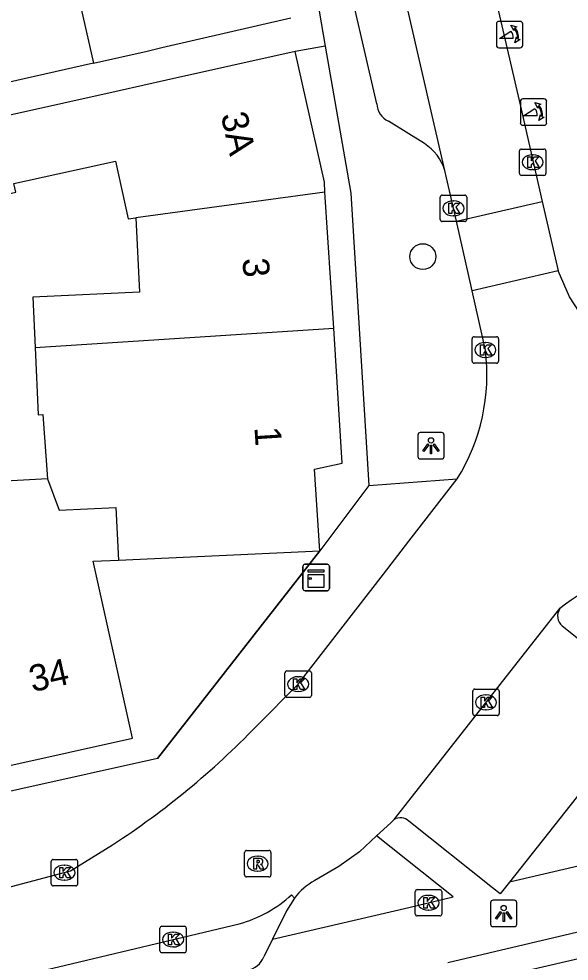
# Model space of a CAD drawing. Extents: x 160861 to 161308, y 384024 to 384878.
# Drawn here: x 160985.24 to 161006.07, y 384696.73 to 384732.38 of the extents above; entities that cross this region are included whole.
import ezdxf

# ---------------------------------------------------------------- set-up
doc = ezdxf.new("R2010")
doc.units = 0
for name, color, linetype in [('IMGEO_Boom', 7, 'Continuous'), ('IMGEO_Kast', 7, 'Continuous'), ('IMGEO_Kolk', 7, 'Continuous'), ('IMGEO_Lichtpunt', 7, 'Continuous'), ('IMGEO_Muur', 7, 'Continuous'), ('IMGEO_Pand', 7, 'Continuous'), ('IMGEO_Pand_nummerreeks', 7, 'Continuous'), ('IMGEO_Parkeervlak_open', 7, 'Continuous'), ('IMGEO_Poller', 7, 'Continuous'), ('IMGEO_Rijbaan_lokaal_open', 7, 'Continuous'), ('IMGEO_Rioolput', 7, 'Continuous'), ('IMGEO_Voetpad_open', 7, 'Continuous')]:
    doc.layers.add(name, color=color, linetype=linetype)

msp = doc.modelspace()

# ---------------------------------------------------------------- linework, layer by layer
at = {"layer": 'IMGEO_Boom'}
msp.add_circle((161000.528, 384723.383), 0.489, dxfattribs=at)
at = {"layer": 'IMGEO_Kast'}
for p, q in [((160995.991, 384710.823), (160995.991, 384711.664)), ((160995.991, 384711.664), (160995.991, 384710.823)), ((160996.066, 384711.748), (160996.907, 384711.748)), ((160996.907, 384711.748), (160996.066, 384711.748)), ((160996.991, 384711.673), (160996.991, 384710.832)), ((160996.991, 384710.832), (160996.991, 384711.673)), ((160996.916, 384710.748), (160996.075, 384710.748)), ((160996.075, 384710.748), (160996.916, 384710.748))]:
    msp.add_line(p, q, dxfattribs=at)
for points in [[(160996.186, 384711.538), (160996.786, 384711.538), (160996.786, 384711.453), (160996.186, 384711.453), (160996.186, 384711.538)], [(160996.186, 384711.363), (160996.786, 384711.363), (160996.786, 384710.874), (160996.186, 384710.874), (160996.186, 384711.363)]]:
    msp.add_lwpolyline(points, dxfattribs=at)
msp.add_circle((160996.27, 384711.212), 0.0377, dxfattribs=at)
for centre, start, end in [((160996.069, 384711.67), 92.4484, 184.2845), ((160996.069, 384711.67), 92.4484, 184.2845), ((160996.913, 384711.67), 2.4484, 94.2845), ((160996.913, 384711.67), 2.4484, 94.2845), ((160996.069, 384710.826), 182.4484, 274.2845), ((160996.069, 384710.826), 182.4484, 274.2845), ((160996.913, 384710.826), 272.4484, 4.2845), ((160996.913, 384710.826), 272.4484, 4.2845)]:
    msp.add_arc(centre, 0.0779, start, end, dxfattribs=at)
at = {"layer": 'IMGEO_Kolk'}
for p, q in [((161004.187, 384726.528), (161004.187, 384727.38)), ((161004.262, 384727.454), (161005.114, 384727.454)), ((161004.675, 384727.234), (161004.7, 384727.234)), ((161005.188, 384727.38), (161005.188, 384726.528)), ((161004.698, 384726.674), (161004.673, 384726.674)), ((161005.114, 384726.454), (161004.262, 384726.454)), ((161001.189, 384724.785), (161001.189, 384725.637)), ((161001.264, 384725.711), (161002.116, 384725.711)), ((161001.677, 384725.491), (161001.702, 384725.491)), ((161002.19, 384725.637), (161002.19, 384724.785)), ((161002.116, 384724.711), (161001.264, 384724.711)), ((161001.7, 384724.931), (161001.675, 384724.931)), ((161002.395, 384719.428), (161002.395, 384720.28)), ((161002.47, 384720.354), (161003.322, 384720.354)), ((161002.883, 384720.134), (161002.908, 384720.134)), ((161003.396, 384720.28), (161003.396, 384719.428)), ((161003.322, 384719.354), (161002.47, 384719.354)), ((161002.906, 384719.574), (161002.881, 384719.574)), ((160995.312, 384706.788), (160995.312, 384707.64)), ((160995.387, 384707.714), (160996.239, 384707.714)), ((160996.313, 384707.64), (160996.313, 384706.788)), ((160995.8, 384707.494), (160995.825, 384707.494)), ((160995.823, 384706.934), (160995.798, 384706.934)), ((161002.419, 384706.098), (161002.419, 384706.95)), ((161002.494, 384707.024), (161003.346, 384707.024)), ((161003.42, 384706.95), (161003.42, 384706.098)), ((160996.239, 384706.714), (160995.387, 384706.714)), ((161002.907, 384706.804), (161002.932, 384706.804)), ((161002.93, 384706.244), (161002.905, 384706.244)), ((161003.346, 384706.024), (161002.494, 384706.024)), ((160986.463, 384699.656), (160986.463, 384700.508)), ((160986.538, 384700.582), (160987.39, 384700.582)), ((160987.464, 384700.508), (160987.464, 384699.656)), ((160986.951, 384700.362), (160986.976, 384700.362)), ((160986.974, 384699.802), (160986.949, 384699.802)), ((160987.39, 384699.582), (160986.538, 384699.582)), ((161000.32, 384699.444), (161001.172, 384699.444)), ((161000.245, 384698.518), (161000.245, 384699.37)), ((161000.733, 384699.224), (161000.758, 384699.224)), ((161001.246, 384699.37), (161001.246, 384698.518)), ((161001.172, 384698.444), (161000.32, 384698.444)), ((161000.756, 384698.664), (161000.731, 384698.664)), ((160990.576, 384697.127), (160990.576, 384697.979)), ((160990.651, 384698.053), (160991.503, 384698.053)), ((160991.577, 384697.979), (160991.577, 384697.127)), ((160991.064, 384697.833), (160991.089, 384697.833)), ((160991.087, 384697.273), (160991.062, 384697.273)), ((160991.503, 384697.053), (160990.651, 384697.053))]:
    msp.add_line(p, q, dxfattribs=at)
for points in [[(161004.187, 384726.528), (161004.187, 384727.38)], [(161004.262, 384727.454), (161005.114, 384727.454)], [(161005.188, 384727.38), (161005.188, 384726.528)], [(161004.508, 384727.154), (161004.631, 384727.154), (161004.631, 384727.003), (161004.761, 384727.154), (161004.925, 384727.154), (161004.779, 384727.003), (161004.932, 384726.754), (161004.78, 384726.754), (161004.695, 384726.918), (161004.631, 384726.851), (161004.631, 384726.754), (161004.508, 384726.754), (161004.508, 384727.154)], [(161005.114, 384726.454), (161004.262, 384726.454)], [(161001.189, 384724.785), (161001.189, 384725.637)], [(161001.264, 384725.711), (161002.116, 384725.711)], [(161001.51, 384725.411), (161001.633, 384725.411), (161001.633, 384725.26), (161001.763, 384725.411), (161001.927, 384725.411), (161001.781, 384725.26), (161001.934, 384725.011), (161001.782, 384725.011), (161001.697, 384725.175), (161001.633, 384725.108), (161001.633, 384725.011), (161001.51, 384725.011), (161001.51, 384725.411)], [(161002.19, 384725.637), (161002.19, 384724.785)], [(161002.116, 384724.711), (161001.264, 384724.711)], [(161002.395, 384719.428), (161002.395, 384720.28)], [(161002.47, 384720.354), (161003.322, 384720.354)], [(161002.716, 384720.054), (161002.839, 384720.054), (161002.839, 384719.903), (161002.969, 384720.054), (161003.133, 384720.054), (161002.987, 384719.903), (161003.14, 384719.654), (161002.988, 384719.654), (161002.903, 384719.818), (161002.839, 384719.751), (161002.839, 384719.654), (161002.716, 384719.654), (161002.716, 384720.054)], [(161003.396, 384720.28), (161003.396, 384719.428)], [(161003.322, 384719.354), (161002.47, 384719.354)], [(160995.312, 384706.788), (160995.312, 384707.64)], [(160995.387, 384707.714), (160996.239, 384707.714)], [(160996.313, 384707.64), (160996.313, 384706.788)], [(160995.633, 384707.414), (160995.756, 384707.414), (160995.756, 384707.263), (160995.886, 384707.414), (160996.05, 384707.414), (160995.904, 384707.263), (160996.057, 384707.014), (160995.905, 384707.014), (160995.82, 384707.178), (160995.756, 384707.111), (160995.756, 384707.014), (160995.633, 384707.014), (160995.633, 384707.414)], [(161002.419, 384706.098), (161002.419, 384706.95)], [(161002.494, 384707.024), (161003.346, 384707.024)], [(161003.42, 384706.95), (161003.42, 384706.098)], [(160996.239, 384706.714), (160995.387, 384706.714)], [(161002.74, 384706.724), (161002.863, 384706.724), (161002.863, 384706.573), (161002.993, 384706.724), (161003.157, 384706.724), (161003.011, 384706.573), (161003.164, 384706.324), (161003.012, 384706.324), (161002.927, 384706.488), (161002.863, 384706.421), (161002.863, 384706.324), (161002.74, 384706.324), (161002.74, 384706.724)], [(161003.346, 384706.024), (161002.494, 384706.024)], [(160986.463, 384699.656), (160986.463, 384700.508)], [(160986.538, 384700.582), (160987.39, 384700.582)], [(160987.464, 384700.508), (160987.464, 384699.656)], [(160986.784, 384700.282), (160986.907, 384700.282), (160986.907, 384700.131), (160987.037, 384700.282), (160987.201, 384700.282), (160987.055, 384700.131), (160987.208, 384699.882), (160987.056, 384699.882), (160986.971, 384700.046), (160986.907, 384699.979), (160986.907, 384699.882), (160986.784, 384699.882), (160986.784, 384700.282)], [(160987.39, 384699.582), (160986.538, 384699.582)], [(161000.32, 384699.444), (161001.172, 384699.444)], [(161000.245, 384698.518), (161000.245, 384699.37)], [(161000.566, 384699.144), (161000.689, 384699.144), (161000.689, 384698.993), (161000.819, 384699.144), (161000.983, 384699.144), (161000.837, 384698.993), (161000.99, 384698.744), (161000.838, 384698.744), (161000.753, 384698.908), (161000.689, 384698.841), (161000.689, 384698.744), (161000.566, 384698.744), (161000.566, 384699.144)], [(161001.246, 384699.37), (161001.246, 384698.518)], [(161001.172, 384698.444), (161000.32, 384698.444)], [(160990.576, 384697.127), (160990.576, 384697.979)], [(160990.651, 384698.053), (160991.503, 384698.053)], [(160991.577, 384697.979), (160991.577, 384697.127)], [(160990.897, 384697.753), (160991.02, 384697.753), (160991.02, 384697.602), (160991.15, 384697.753), (160991.314, 384697.753), (160991.168, 384697.602), (160991.321, 384697.353), (160991.169, 384697.353), (160991.084, 384697.517), (160991.02, 384697.45), (160991.02, 384697.353), (160990.897, 384697.353), (160990.897, 384697.753)], [(160991.503, 384697.053), (160990.651, 384697.053)]]:
    msp.add_lwpolyline(points, dxfattribs=at)
for centre, start, end in [((161004.264, 384727.378), 91.552, 178.448), ((161004.264, 384727.378), 91.552, 178.448), ((161005.112, 384727.378), 1.552, 88.448), ((161005.112, 384727.378), 1.552, 88.448), ((161004.264, 384726.53), 181.552, 268.448), ((161004.264, 384726.53), 181.552, 268.448), ((161005.112, 384726.53), 271.552, 358.448), ((161005.112, 384726.53), 271.552, 358.448), ((161001.266, 384725.635), 91.552, 178.448), ((161001.266, 384725.635), 91.552, 178.448), ((161002.114, 384725.635), 1.552, 88.448), ((161002.114, 384725.635), 1.552, 88.448), ((161001.266, 384724.787), 181.552, 268.448), ((161001.266, 384724.787), 181.552, 268.448), ((161002.114, 384724.787), 271.552, 358.448), ((161002.114, 384724.787), 271.552, 358.448), ((161002.472, 384720.278), 91.552, 178.448), ((161002.472, 384720.278), 91.552, 178.448), ((161003.32, 384720.278), 1.552, 88.448), ((161003.32, 384720.278), 1.552, 88.448), ((161002.472, 384719.43), 181.552, 268.448), ((161002.472, 384719.43), 181.552, 268.448), ((161003.32, 384719.43), 271.552, 358.448), ((161003.32, 384719.43), 271.552, 358.448), ((160995.389, 384707.638), 91.552, 178.448), ((160995.389, 384707.638), 91.552, 178.448), ((160996.237, 384707.638), 1.552, 88.448), ((160996.237, 384707.638), 1.552, 88.448), ((161002.496, 384706.948), 91.552, 178.448), ((161002.496, 384706.948), 91.552, 178.448), ((161003.344, 384706.948), 1.552, 88.448), ((161003.344, 384706.948), 1.552, 88.448), ((160995.389, 384706.79), 181.552, 268.448), ((160995.389, 384706.79), 181.552, 268.448), ((160996.237, 384706.79), 271.552, 358.448), ((160996.237, 384706.79), 271.552, 358.448), ((161002.496, 384706.1), 181.552, 268.448), ((161002.496, 384706.1), 181.552, 268.448), ((161003.344, 384706.1), 271.552, 358.448), ((161003.344, 384706.1), 271.552, 358.448), ((160986.54, 384700.506), 91.552, 178.448), ((160986.54, 384700.506), 91.552, 178.448), ((160987.388, 384700.506), 1.552, 88.448), ((160987.388, 384700.506), 1.552, 88.448), ((160986.54, 384699.658), 181.552, 268.448), ((160986.54, 384699.658), 181.552, 268.448), ((160987.388, 384699.658), 271.552, 358.448), ((160987.388, 384699.658), 271.552, 358.448), ((161000.322, 384699.368), 91.552, 178.448), ((161000.322, 384699.368), 91.552, 178.448), ((161001.17, 384699.368), 1.552, 88.448), ((161001.17, 384699.368), 1.552, 88.448), ((161000.322, 384698.52), 181.552, 268.448), ((161000.322, 384698.52), 181.552, 268.448), ((161001.17, 384698.52), 271.552, 358.448), ((161001.17, 384698.52), 271.552, 358.448), ((160990.653, 384697.977), 91.552, 178.448), ((160990.653, 384697.977), 91.552, 178.448), ((160991.501, 384697.977), 1.552, 88.448), ((160991.501, 384697.977), 1.552, 88.448), ((160990.653, 384697.129), 181.552, 268.448), ((160990.653, 384697.129), 181.552, 268.448), ((160991.501, 384697.129), 271.552, 358.448), ((160991.501, 384697.129), 271.552, 358.448)]:
    msp.add_arc(centre, 0.0765, start, end, dxfattribs=at)
for centre, major_axis, ratio, start_param, end_param in [((161004.674, 384726.954), (-0.387, 0.002), 0.722429, 4.712389, 7.853982), ((161004.699, 384726.954), (-0.39, 0.002), 0.717154, 1.570796, 4.712389), ((161001.676, 384725.211), (-0.387, 0.002), 0.722429, 4.712389, 7.853982), ((161001.701, 384725.211), (-0.39, 0.002), 0.717154, 1.570796, 4.712389), ((161002.882, 384719.854), (-0.387, 0.002), 0.722429, 4.712389, 7.853982), ((161002.907, 384719.854), (-0.39, 0.002), 0.717154, 1.570796, 4.712389), ((160995.799, 384707.214), (-0.387, 0.002), 0.722429, 4.712389, 7.853982), ((160995.824, 384707.214), (-0.39, 0.002), 0.717154, 1.570796, 4.712389), ((161002.906, 384706.524), (-0.387, 0.002), 0.722429, 4.712389, 7.853982), ((161002.931, 384706.524), (-0.39, 0.002), 0.717154, 1.570796, 4.712389), ((160986.95, 384700.082), (-0.387, 0.002), 0.722429, 4.712389, 7.853982), ((160986.975, 384700.082), (-0.39, 0.002), 0.717154, 1.570796, 4.712389), ((161000.732, 384698.944), (-0.387, 0.002), 0.722429, 4.712389, 7.853982), ((161000.757, 384698.944), (-0.39, 0.002), 0.717154, 1.570796, 4.712389), ((160991.063, 384697.553), (-0.387, 0.002), 0.722429, 4.712389, 7.853982), ((160991.088, 384697.553), (-0.39, 0.002), 0.717154, 1.570796, 4.712389)]:
    msp.add_ellipse(centre, major_axis=major_axis, ratio=ratio, start_param=start_param, end_param=end_param, dxfattribs=at)
at = {"layer": 'IMGEO_Lichtpunt'}
for p, q in [((161000.34, 384716.635), (161000.34, 384715.828)), ((161000.34, 384716.635), (161000.34, 384715.828)), ((161001.242, 384716.73), (161000.434, 384716.73)), ((161001.242, 384716.73), (161000.434, 384716.73)), ((161001.336, 384715.828), (161001.336, 384716.635)), ((161001.336, 384715.828), (161001.336, 384716.635)), ((161000.434, 384715.734), (161001.242, 384715.734)), ((161000.434, 384715.734), (161001.242, 384715.734)), ((161003.993, 384699.04), (161003.185, 384699.04)), ((161003.993, 384699.04), (161003.185, 384699.04)), ((161003.091, 384698.945), (161003.091, 384698.138)), ((161003.091, 384698.945), (161003.091, 384698.138)), ((161004.087, 384698.138), (161004.087, 384698.945)), ((161004.087, 384698.138), (161004.087, 384698.945)), ((161003.185, 384698.044), (161003.993, 384698.044)), ((161003.185, 384698.044), (161003.993, 384698.044))]:
    msp.add_line(p, q, dxfattribs=at)
for points in [[(161000.714, 384716.299), (161000.753, 384716.271), (161000.565, 384716.009), (161000.527, 384716.036), (161000.714, 384716.299)], [(161000.816, 384716.251), (161000.863, 384716.251), (161000.863, 384715.929), (161000.816, 384715.929), (161000.816, 384716.251)], [(161000.926, 384716.271), (161000.964, 384716.298), (161001.151, 384716.036), (161001.112, 384716.008), (161000.926, 384716.271)], [(161003.465, 384698.609), (161003.504, 384698.581), (161003.316, 384698.319), (161003.278, 384698.346), (161003.465, 384698.609)], [(161003.567, 384698.561), (161003.614, 384698.561), (161003.614, 384698.239), (161003.567, 384698.239), (161003.567, 384698.561)], [(161003.677, 384698.581), (161003.715, 384698.608), (161003.902, 384698.346), (161003.863, 384698.318), (161003.677, 384698.581)]]:
    msp.add_lwpolyline(points, dxfattribs=at)
for centre in [(161000.839, 384716.433), (161003.59, 384698.743)]:
    msp.add_circle(centre, 0.0994, dxfattribs=at)
for centre, start, end in [((161000.434, 384716.635), 90, 180), ((161000.434, 384716.635), 90, 180), ((161001.242, 384716.635), 0, 90), ((161001.242, 384716.635), 0, 90), ((161000.434, 384715.828), 180, 270), ((161000.434, 384715.828), 180, 270), ((161001.242, 384715.828), 270, 0), ((161001.242, 384715.828), 270, 360), ((161003.185, 384698.945), 90, 180), ((161003.185, 384698.945), 90, 180), ((161003.993, 384698.945), 0, 90), ((161003.993, 384698.945), 0, 90), ((161003.185, 384698.138), 180, 270), ((161003.185, 384698.138), 180, 270), ((161003.993, 384698.138), 270, 0), ((161003.993, 384698.138), 270, 360)]:
    msp.add_arc(centre, 0.0946, start, end, dxfattribs=at)
at = {"layer": 'IMGEO_Muur'}
msp.add_lwpolyline([(160990.485, 384704.401), (160996.631, 384712.258)], dxfattribs=at)
at = {"layer": 'IMGEO_Pand'}
for points in [[(160986.8, 384736.205), (160987.465, 384733.321), (160988.07, 384730.697)], [(160988.07, 384730.697), (160990.089, 384731.162), (160990.655, 384731.292), (160995.527, 384732.415)], [(160995.703, 384731.143), (160990.823, 384730.057), (160989.029, 384729.658), (160982.734, 384728.258)], [(160996.826, 384725.82), (160996.802, 384726.203), (160995.703, 384731.143)], [(160982.734, 384728.258), (160983.361, 384725.436), (160985.122, 384725.827), (160985.052, 384726.144), (160988.896, 384727), (160989.382, 384724.816), (160989.67, 384724.855)], [(160996.826, 384725.82), (160989.67, 384724.855)], [(160997.156, 384720.674), (160996.826, 384725.82)], [(160989.67, 384724.855), (160989.802, 384722.041), (160985.765, 384721.851), (160985.854, 384719.951)], [(160985.854, 384719.951), (160989.952, 384720.213), (160997.156, 384720.674)], [(160996.631, 384712.258), (160996.43, 384715.341), (160997.482, 384715.574), (160997.156, 384720.674)], [(160985.854, 384719.951), (160985.975, 384717.403), (160986.143, 384717.414), (160986.323, 384714.974)], [(160986.323, 384714.974), (160984.491, 384714.881), (160984.343, 384715.546), (160982.183, 384715.066)], [(160986.323, 384714.974), (160986.768, 384713.795), (160988.913, 384713.896), (160989.006, 384711.905)], [(160989.006, 384711.905), (160996.631, 384712.258)], [(160984.675, 384704.086), (160989.534, 384705.167), (160988.046, 384711.86), (160989.006, 384711.905)], [(161001.694, 384695.742), (161006.641, 384696.888)]]:
    msp.add_lwpolyline(points, dxfattribs=at)
at = {"layer": 'IMGEO_Parkeervlak_open'}
for points in [[(161005.803, 384709.414), (161009.282, 384706.645), (161003.807, 384699.717)], [(160995.668, 384699.122), (160995.374, 384698.633), (160994.843, 384697.57)]]:
    msp.add_lwpolyline(points, dxfattribs=at)
msp.add_arc((161006.124, 384709.79), 0.494, 145.4216, 229.5159, dxfattribs=at)
at = {"layer": 'IMGEO_Poller'}
for p, q in [((161003.312, 384732.187), (161003.312, 384731.38)), ((161003.312, 384732.187), (161003.312, 384731.38)), ((161004.214, 384732.282), (161003.406, 384732.282)), ((161004.214, 384732.282), (161003.406, 384732.282)), ((161004.308, 384731.38), (161004.308, 384732.187)), ((161004.308, 384731.38), (161004.308, 384732.187)), ((161003.406, 384731.285), (161004.214, 384731.285)), ((161003.406, 384731.285), (161004.214, 384731.285)), ((161005.122, 384729.35), (161004.314, 384729.35)), ((161005.122, 384729.35), (161004.314, 384729.35)), ((161004.22, 384729.255), (161004.22, 384728.448)), ((161004.22, 384729.255), (161004.22, 384728.448)), ((161005.216, 384728.448), (161005.216, 384729.255)), ((161005.216, 384728.448), (161005.216, 384729.255)), ((161004.314, 384728.353), (161005.122, 384728.353)), ((161004.314, 384728.353), (161005.122, 384728.353))]:
    msp.add_line(p, q, dxfattribs=at)
for points in [[(161003.947, 384731.638), (161003.434, 384731.638), (161003.864, 384731.913)], [(161003.991, 384732.011), (161003.979, 384731.938), (161003.854, 384732.143)], [(161003.854, 384732.143), (161004.085, 384732.077), (161004.014, 384732.045)], [(161004.007, 384731.466), (161004.073, 384731.697), (161004.103, 384731.629)], [(161004.139, 384731.602), (161004.211, 384731.591), (161004.007, 384731.466)], [(161004.855, 384728.706), (161004.342, 384728.706), (161004.772, 384728.981)], [(161004.899, 384729.079), (161004.887, 384729.006), (161004.762, 384729.211)], [(161004.762, 384729.211), (161004.993, 384729.145), (161004.922, 384729.113)], [(161004.915, 384728.534), (161004.981, 384728.765), (161005.011, 384728.697)], [(161005.047, 384728.67), (161005.119, 384728.659), (161004.915, 384728.534)]]:
    msp.add_lwpolyline(points, dxfattribs=at)
for centre, radius, start, end in [((161003.406, 384732.187), 0.0946, 90, 180), ((161003.406, 384732.187), 0.0946, 90, 180), ((161004.214, 384732.187), 0.0946, 0, 90), ((161004.214, 384732.187), 0.0946, 0, 90), ((161003.619, 384731.688), 0.332, 351.3247, 42.4854), ((161003.633, 384731.698), 0.476, 351.7527, 41.1691), ((161003.633, 384731.698), 0.516, 349.3569, 42.2912), ((161003.406, 384731.38), 0.0946, 180, 270), ((161003.406, 384731.38), 0.0946, 180, 270), ((161004.214, 384731.38), 0.0946, 270, 0), ((161004.214, 384731.38), 0.0946, 270, 0), ((161004.314, 384729.255), 0.0946, 90, 180), ((161004.314, 384729.255), 0.0946, 90, 180), ((161005.122, 384729.255), 0.0946, 0, 90), ((161005.122, 384729.255), 0.0946, 0, 90), ((161004.527, 384728.756), 0.332, 351.3247, 42.4854), ((161004.541, 384728.766), 0.476, 351.7527, 41.1691), ((161004.541, 384728.766), 0.516, 349.3569, 42.2912), ((161004.314, 384728.448), 0.0946, 180, 270), ((161004.314, 384728.448), 0.0946, 180, 270), ((161005.122, 384728.448), 0.0946, 270, 0), ((161005.122, 384728.448), 0.0946, 270, 0)]:
    msp.add_arc(centre, radius, start, end, dxfattribs=at)
at = {"layer": 'IMGEO_Rijbaan_lokaal_open'}
for points in [[(161001.366, 384726.644), (161000, 384732.552), (160995.965, 384750), (160994.782, 384755.119)], [(160999.889, 384747.841), (161000, 384747.359), (161003.189, 384733.536), (161004.207, 384729.126), (161005.05, 384725.472)], [(161001.801, 384724.723), (161001.43, 384726.368), (161001.366, 384726.644)], [(161001.801, 384724.723), (161005.05, 384725.472)], [(161005.05, 384725.472), (161005.657, 384722.841)], [(161002.394, 384722.089), (161001.801, 384724.723)], [(161005.657, 384722.841), (161002.394, 384722.089)], [(161007.185, 384720.166), (161006.075, 384721.859), (161005.657, 384722.841)], [(161002.898, 384719.85), (161002.394, 384722.089)], [(160994.23, 384705.618), (160995.811, 384707.21), (160999.036, 384711.374), (161000, 384712.619), (161001.824, 384714.974)], [(160999.442, 384702.091), (161000, 384702.803), (161005.717, 384710.07)], [(160999.442, 384702.091), (160999.318, 384701.967), (160998.778, 384701.469)], [(160998.778, 384701.469), (160998.129, 384700.872), (160997.347, 384700.315), (160996.44, 384699.783)], [(160984.769, 384699.502), (160987.198, 384700.153), (160988.789, 384701.138)], [(160995.558, 384699.247), (160995.668, 384699.122)], [(160971.03, 384692.792), (160993.576, 384698.147)]]:
    msp.add_lwpolyline(points, dxfattribs=at)
for centre, radius, start, end in [((160995.497, 384718.924), 7.459, 328.0245, 7.132), ((161009.989, 384704.824), 6.765, 92.7034, 129.1598), ((160971.768, 384727.354), 31.256, 302.9937, 315.9409), ((160997.648, 384697.59), 2.503, 118.859, 142.2824), ((160992.333, 384702.723), 4.742, 285.202, 312.8581)]:
    msp.add_arc(centre, radius, start, end, dxfattribs=at)
at = {"layer": 'IMGEO_Rioolput'}
for p, q in [((160993.779, 384699.995), (160993.779, 384700.847)), ((160993.854, 384700.921), (160994.706, 384700.921)), ((160994.78, 384700.847), (160994.78, 384699.995)), ((160994.267, 384700.701), (160994.292, 384700.701)), ((160994.29, 384700.141), (160994.265, 384700.141)), ((160994.706, 384699.921), (160993.854, 384699.921))]:
    msp.add_line(p, q, dxfattribs=at)
for points in [[(160993.779, 384699.995), (160993.779, 384700.847)], [(160993.854, 384700.921), (160994.706, 384700.921)], [(160994.78, 384700.847), (160994.78, 384699.995)], [(160994.368, 384700.619), (160994.116, 384700.621), (160994.116, 384700.221)], [(160994.294, 384700.54), (160994.24, 384700.54), (160994.24, 384700.459)], [(160994.24, 384700.459), (160994.292, 384700.459)], [(160994.116, 384700.221), (160994.24, 384700.221), (160994.24, 384700.383), (160994.251, 384700.383)], [(160994.298, 384700.354), (160994.369, 384700.221), (160994.509, 384700.221), (160994.444, 384700.347)], [(160994.706, 384699.921), (160993.854, 384699.921)]]:
    msp.add_lwpolyline(points, dxfattribs=at)
for centre, radius, start, end in [((160993.856, 384700.845), 0.0765, 91.552, 178.448), ((160993.856, 384700.845), 0.0765, 91.552, 178.448), ((160994.704, 384700.845), 0.0765, 1.552, 88.448), ((160994.704, 384700.845), 0.0765, 1.552, 88.448), ((160994.276, 384700.648), 0.19, 274.7715, 282.9687), ((160994.3, 384700.444), 0.0964, 77.0061, 93.1865), ((160994.314, 384700.501), 0.0378, 276.6634, 79.6772), ((160994.367, 384700.509), 0.109, 350.3612, 89.416), ((160994.365, 384700.509), 0.112, 277.5842, 350.9817), ((160994.25, 384700.33), 0.0533, 26.0293, 88.6989), ((160994.349, 384700.294), 0.108, 29.5134, 73.7905), ((160993.856, 384699.997), 0.0765, 181.552, 268.448), ((160993.856, 384699.997), 0.0765, 181.552, 268.448), ((160994.704, 384699.997), 0.0765, 271.552, 358.448), ((160994.704, 384699.997), 0.0765, 271.552, 358.448)]:
    msp.add_arc(centre, radius, start, end, dxfattribs=at)
for centre, major_axis, ratio, start_param, end_param in [((160994.266, 384700.421), (-0.387, 0.002), 0.722429, 4.712389, 7.853982), ((160994.291, 384700.421), (-0.39, 0.002), 0.717154, 1.570796, 4.712389)]:
    msp.add_ellipse(centre, major_axis=major_axis, ratio=ratio, start_param=start_param, end_param=end_param, dxfattribs=at)
at = {"layer": 'IMGEO_Voetpad_open'}
for points in [[(160998.787, 384729.167), (160993.97, 384750), (160993.604, 384751.585)], [(160996.604, 384732.664), (160996.834, 384731.34)], [(160996.834, 384731.34), (160995.703, 384731.143)], [(160996.834, 384731.34), (160997.799, 384725.788), (160998.487, 384714.721)], [(160988.07, 384730.697), (160974.369, 384727.616), (160973.888, 384730.142)], [(161000.591, 384727.664), (161000, 384728.031), (160999.227, 384728.509)], [(160998.487, 384714.721), (160996.631, 384712.258)], [(160998.487, 384714.721), (161001.824, 384714.974)], [(160996.631, 384712.258), (160990.485, 384704.401), (160980.053, 384702.083), (160979.817, 384703.005)], [(161017.08, 384712.007), (161017.659, 384702.946), (161003.807, 384699.717)], [(161001.472, 384696.684), (161020.098, 384701.072), (161019.614, 384709.69)], [(161003.807, 384699.717), (161003.459, 384699.276), (161003.161, 384699.513), (161000, 384702.03)], [(160994.843, 384697.57), (161000, 384698.766), (161001.675, 384699.162), (160998.778, 384701.469)], [(160994.843, 384697.57), (160994.506, 384696.895)]]:
    msp.add_lwpolyline(points, dxfattribs=at)
for centre, radius, start, end in [((160999.535, 384729.191), 0.749, 181.8583, 245.6824), ((160999.551, 384726.07), 1.903, 17.5643, 56.8912), ((160999.682, 384701.706), 0.454, 45.5845, 121.938), ((160993.749, 384697.198), 0.815, 281.0897, 338.1824)]:
    msp.add_arc(centre, radius, start, end, dxfattribs=at)

# ---------------------------------------------------------------- texts
at = {"layer": 'IMGEO_Pand_nummerreeks'}
for s, rotation, p in [('3A', 282.5418, (160992.877, 384728.745)), ('3', 273.6667, (160993.701, 384723.312)), ('1', 273.6553, (160994.155, 384716.93)), ('34', 12.5438, (160985.751, 384706.906))]:
    msp.add_text(s, height=1, rotation=rotation, dxfattribs=at).set_placement(p)

doc.saveas('drawing.dxf')
